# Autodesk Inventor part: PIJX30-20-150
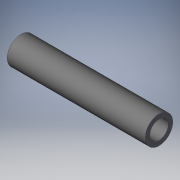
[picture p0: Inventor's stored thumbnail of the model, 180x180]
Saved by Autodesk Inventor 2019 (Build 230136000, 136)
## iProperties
Created: 2022-11
Part Number: PIJX30-20-150
Material: Generic
Catalog Web Link: www.cadenas.de
Description: PIJJ, PIJK, PIJM, PIJW, PIJG, PIJT, PIJB, PIJN, PIJF, PIJP, PIJS, PIJX, PIJU-Resin Pipes - ID and OD Surface Finished
Vendor: MISUMI
Document SubType Name: Modeling
Designer: psAdmin
Manufacturer: MISUMI
Mass: 58.9049 g
Surface Area: 243.473 cm^2
Volume: 58.9049 cm^3
Density: 1 g/cm^3
Appearance: PSOLRGB-242-242-242
Category: PARTsolutions
Company: MISUMI
Title: PIJX30-20-150
Author: Cadenas PARTsolutions
Comments: Resin Pipes - ID and OD Surface Finished
PSOL_IDENT_0: {$CADENAS_DATA/23d-libs/misumi/metric/22_rods_pipes/pijj.prj},259 {VTYP=3D},{NB=PIJX30-20-150},{LINA=
PSOL_IDENT_1: PIJX30-20-150},{NN=PIJJ, PIJK, PIJM, PIJW, PIJG, PIJT, PIJB, PIJN, PIJF, PIJP, PIJS, PIJX, PIJU},{DA
PSOL_IDENT_2: TE=30.06.2021 13:08:38},{GEOMDATE=29.05.2014 00:00:00},{VERSION=},{LINEID=140},{WBVAR=MAT,GRADE,COLO
PSOL_IDENT_3: R,V,L},{WBNUMERIC=V,L}  {NB=PIJX30-20-150},{LINA=PIJX30-20-150},{KT=DUMMY},{PN=PIJX30-20-150},{TYPE=
PSOL_IDENT_4: PIJX},{MAT=ABS},{MATALG= 'P','Polyacetal','MC','MC Nylon','B','Bakelite','F','Fluororesin','PEEK','P
PSOL_IDENT_5: EEK','PPS','PPS','ABS','ABS Resin','UHMWP','Ultra-High-Molecular-Weight-Polyethylene' },{GRADE=S},{G
PSOL_IDENT_6: RADEALG= 'S','Standard' },{COLOR=BE},{COLORALG= 'BE','Beige' },{COL=0.95,0.95,0.95,0.00},{D=30},{V=2
PSOL_IDENT_7: 0},{VALG=16,20,25},{L=150},{LALG=[20:200/1]},{LMIN=20},{LMAX=200}
NB: PIJX30-20-150
NN: PIJJ, PIJK, PIJM, PIJW, PIJG, PIJT, PIJB, PIJN, PIJF, PIJP, PIJS, PIJX, PIJU
NT: Resin Pipes - ID and OD Surface Finished
NBSYN: $PN.
LINA: PIJX30-20-150
CATALOG: Misumi
PN: PIJX30-20-150
MAT: ABS Resin
GRADE: Standard
COLOR: Beige
D: 30
V: 20
L: 150
SUPPLIER: MISUMI
ARTICLENO: PIJX30-20-150
BOMINFO: PIJX30-20-150
CREATOR: CADENAS GmbH
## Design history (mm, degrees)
sketch "Sketch_1"
  geometry: L1 (150, 0)-(0, 0); L2 (0, 10)-(150, 10); L3 (150, 10)-(150, 15); L4 (150, 15)-(0, 15); L5 (0, 15)-(0, 10)
  constraints: 10 end point
revolve "Revolution1" sketch "Sketch_1" stored, may be unused: angle "d0" = 360 deg
body "Solid1"
